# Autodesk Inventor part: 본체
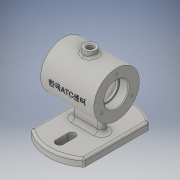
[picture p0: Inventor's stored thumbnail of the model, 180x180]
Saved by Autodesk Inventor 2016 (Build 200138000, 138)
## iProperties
Created: 2017-12
Part Number: 본체
Material: 일반
Document SubType Name: Modeling
Designer: 605-04
Density: 1 g/cm^3
Appearance: 기본값
Author: 605-04
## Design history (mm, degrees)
sketch "스케치1"
  geometry: L1 (35, 0)-(-35, 0); L2 (35, 16)-(23, 16); L3 (23, 16)-(23, 14); L4 (23, 14)-(20, 14); L5 (20, 14)-(20, 25); L6 (20, 25)-(-20, 25); L7 (-20, 25)-(-20, 14); L8 (-20, 14)-(-23, 14); L9 (-23, 14)-(-23, 16); L10 (-23, 16)-(-35, 16); L11 (-35, 16)-(-35, 30); L12 (-35, 30)-(35, 30); L13 (35, 30)-(35, 16); 1 further point
  constraints: 26 end point, 9 perpendicular, 4 point on line, 2 horizontal, 2 vertical alignment, 1 midpoint
  dimensions: "d0" = 70 distance of L1.start L1.end; "d1" = 35 distance of point (0, 0) L1.start; "d2" = 32 diameter of L2 L1; "d3" = 28 diameter of L4 L1; "d4" = 50 diameter of L6 L1; "d5" = 12 distance between parallel lines of L3 L13; "d6" = 60 diameter of L12 L1; "d7" = 3 distance between parallel lines of L5 L3; "d8" = 40 distance between parallel lines of L7 L5; "d9" = 3 distance between parallel lines of L9 L7
revolve "회전1" sketch "스케치1" stored, may be unused: angle "d10" = 90 deg
node "작업 평면2"
sketch "스케치2"
  geometry: L1 (-35, 42.426)-(-35, -42.426); L2 (35, 42.426)-(35, -42.426); A1 r 55 centre (0, 0) between (35, 42.426) and (-35, 42.426); A2 r 55 centre (0, 0) between (-35, -42.426) and (35, -42.426); 1 further point
  constraints: 4 end point, 4 point on circle, 2 centre point, 2 vertical, 1 coincident, 1 concentric, 1 parallel
  dimensions: "d13" = 70 distance between parallel lines of L2 L1; "d14" = 55 radius of A1
extrude "돌출1" join sketch "스케치2" distance "d15" = 10; taper "d16" = 0 deg
sketch "스케치3"
  geometry: L1 (-15, 0)-(15, 0); L2 (-15, -5)-(15, -5); L3 (15, 5)-(-15, 5); A1 r 5 centre (-15, 0) between (-15, 5) and (-15, -5); A2 r 5 centre (15, 0) between (15, -5) and (15, 5); 2 further points
  constraints: 8 end point, 4 point on circle, 4 tangent, 2 centre point, 1 coincident, 1 horizontal, 1 midpoint, 1 parallel
  dimensions: "d17" = 30 distance of L1.start L1.end; "d19" = 5 radius of A2
extrude "돌출2" join sketch "스케치3" stored distance "d20" = 10; taper "d21" = 0 deg; dims "d11" = -62
sketch "스케치4"
  geometry: L1 (0, 40)-(0, 24); L2 (-5, 40)-(-5, 24); L3 (5, 24)-(5, 40); A1 r 5 centre (0, 40) between (5, 40) and (-5, 40); A2 r 5 centre (0, 24) between (-5, 24) and (5, 24); 2 further points
  constraints: 8 end point, 4 point on circle, 4 tangent, 2 centre point, 1 midpoint, 1 parallel, 1 vertical, 1 vertical alignment
  dimensions: "d22" = 16 distance of L1.start L1.end; "d23" = 10 diameter of A2; "d24" = 24 distance of point (0, 0) L1.end
extrude "돌출3" cut sketch "스케치4" distance "d25" = 10; taper "d26" = 0 deg
node "작업 평면3"
sketch "스케치5"
  geometry: L1 (35, 30)-(-35, 30) reference; L2 (-35, 30)-(-35, -30) reference; 2 further points
  constraints: 1 other
  dimensions: "d27" = 30 distance from line of point (0, 0) L1; "d28" = 35 distance from line of point (0, 0) L2
feature "엠보싱1" sketch "스케치5" dims "d0" = 70, "d1" = 35, "d2" = 32, "d3" = 28, "d4" = 50, "d5" = 12, "d6" = 60, "d7" = 3, "d8" = 40, "d9" = 3, "d13" = 70, "d14" = 55, "d29" = 0.5, "d30" = 0
node "작업 평면4"
sketch "스케치6"
  geometry: C1 r 8 at (0, 0); 1 further point
  constraints: 1 centre point, 1 coincident
  dimensions: "d32" = 16 diameter of C1
extrude "돌출4" join sketch "스케치6" stored distance "d33" = 10; taper "d34" = 0 deg
hole "구멍1" diameter "d37" = 8; stored, may be unused: countersink angle "d41" = 90 deg, drill point angle "d43" = 0 deg; dims "d35" = 10, "d36" = 10, "d38" = 6, "d39" = 4, "d40" = 2, "d42" = 8
sketch "스케치7"
  geometry: 2 further points
  constraints: 1 horizontal alignment
  dimensions: "d44" = 23 distance of point (0, 0) point (-23, 0)
hole "구멍2" sketch "스케치7" at (-23, 0) diameter "d45" = 3.242; stored, may be unused: countersink angle "d49" = 90 deg, drill point angle "d51" = 120 deg; dims "d46" = 8, "d47" = 4, "d48" = 2, "d50" = 10
fillet "모깎기1" dims "d55" = 5
fillet "모깎기2" dims "d56" = 3
fillet "모깎기3" dims "d57" = 3
fillet "모깎기4" dims "d58" = 0.3
chamfer "모따기1" distance "d59" = 1; stored, may be unused: second distance "d60" = 2, angle "d61" = 45 deg
node "솔리드1"
mirror "대칭1"
pattern_circular "원형 패턴1" dims angle "d53" = 360 deg
mirror "대칭2"
other parameters: "d31" = 37
